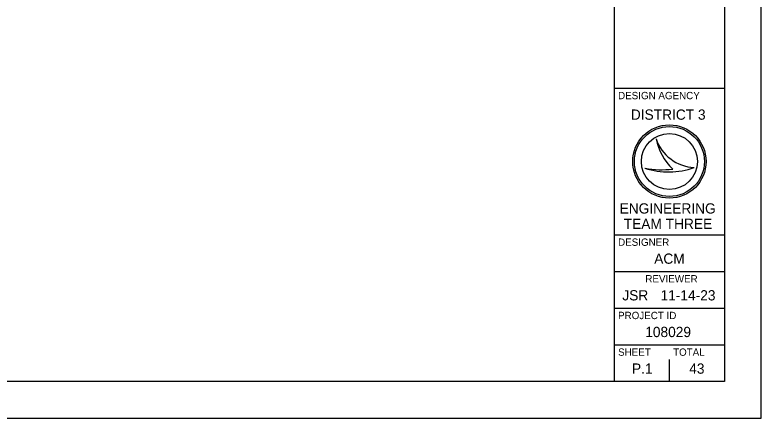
# Model space of a CAD drawing. Extents: x 0 to 34, y 0 to 22.
# Drawn here: x 23.83 to 34, y 0 to 5.5 of the extents above; entities that cross this region are included whole.
import ezdxf

# ---------------------------------------------------------------- set-up
doc = ezdxf.new("R2010")
doc.units = 0
for name, color, linetype in [('SH_Border', 7, 'Continuous'), ('SH_Cut_Line', 7, 'Continuous'), ('SH_Data', 7, 'Continuous')]:
    doc.layers.add(name, color=color, linetype=linetype)

msp = doc.modelspace()

# ---------------------------------------------------------------- linework, layer by layer
at = {"layer": 'SH_Border'}
for p, q in [((32, 0.5), (32, 21.5)), ((32, 4.5), (33.5, 4.5)), ((32, 2.5), (33.5, 2.5)), ((32, 2), (33.5, 2)), ((32, 1.5), (33.5, 1.5)), ((32, 1), (33.5, 1))]:
    msp.add_line(p, q, dxfattribs=at)
msp.add_lwpolyline([(1.5, 21.5), (33.5, 21.5), (33.5, 0.5), (1.5, 0.5)], close=True, dxfattribs=at)
at = {"layer": 'SH_Cut_Line'}
msp.add_lwpolyline([(0, 0), (34, 0), (34, 22), (0, 22)], close=True, dxfattribs=at)
at = {"layer": 'SH_Data'}
for p, q in [((32.567, 3.81), (32.567, 3.81)), ((32.75, 3.5), (32.75, 3.5)), ((32.417, 3.41), (32.417, 3.41)), ((33.087, 3.419), (33.087, 3.419)), ((32.75, 0.5), (32.75, 0.8)), ((32.375, 0.675), (32.375, 0.675))]:
    msp.add_line(p, q, dxfattribs=at)
for radius in [0.5, 0.477, 0.477, 0.382]:
    msp.add_circle((32.75, 3.5), radius, dxfattribs=at)
for centre, radius, start, end in [((33.116, 3.998), 0.58, 198.9257, 198.9319), ((33.347, 3.97), 0.796, 191.6379, 191.6421), ((33.116, 3.998), 0.58, 198.9319, 267.1657), ((33.347, 3.97), 0.796, 191.6421, 226.0947), ((32.739, 4.37), 1.013, 251.4576, 290.0832), ((32.648, 4.654), 1.266, 259.4964, 259.4995), ((32.739, 4.37), 1.013, 251.4527, 251.4576), ((32.648, 4.654), 1.266, 259.4995, 276.6672)]:
    msp.add_arc(centre, radius, start, end, dxfattribs=at)

# ---------------------------------------------------------------- texts
for s, height, p in [('DESIGN AGENCY', 0.1, (32.05, 4.35)), ('DISTRICT 3', 0.14, (32.224, 4.07)), ('ENGINEERING', 0.14, (32.071, 2.79)), ('TEAM THREE', 0.14, (32.127, 2.58)), ('DESIGNER', 0.1, (32.05, 2.35)), ('ACM', 0.14, (32.543, 2.105)), ('REVIEWER', 0.1, (32.422, 1.85)), ('JSR', 0.14, (32.108, 1.605)), ('11-14-23', 0.14, (32.629, 1.605)), ('PROJECT ID', 0.1, (32.05, 1.35)), ('108029', 0.14, (32.42, 1.105)), ('SHEET', 0.1, (32.05, 0.85)), ('TOTAL', 0.1, (32.8, 0.85)), ('P.1', 0.14, (32.24, 0.605)), ('43', 0.14, (33.02, 0.605))]:
    msp.add_text(s, height=height, dxfattribs=at).set_placement(p)

doc.saveas('drawing.dxf')
